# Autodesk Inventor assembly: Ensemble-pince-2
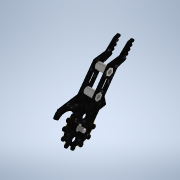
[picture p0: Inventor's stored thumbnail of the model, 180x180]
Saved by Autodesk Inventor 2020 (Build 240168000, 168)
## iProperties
Created: 2021-10
Part Number: Ensemble-pince-2
Document SubType Name: Assembly
Designer: bruno
Author: bruno
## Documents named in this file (4)
- C:\Users\bruno\Documents\1-Cours-2021-22\1SI\Challenge-2021\Pince-Inventor\Ensemble-pince-2.iam
- C:\Users\bruno\Documents\1-Cours-2021-22\1SI\Challenge-2021\Pince-Inventor\Ensemble-doigt-2.iam
- C:\Users\bruno\Documents\1-Cours-2021-22\1SI\Challenge-2021\Pince-Inventor\pince-2.ipt
- C:\Users\bruno\Documents\Inventor\Content Center Files\R2020\fr-FR\ANSI B18.6.7M(01)\ANSI B18.6.7M - M3x0,5 x 5(5).ipt
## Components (5 placed, 3 different names)
1. Ensemble-doigt-2:1 [sub-assembly] — Logement:1, Angle:1, Placage:5, Placage:6
2. pince-2:1 — Logement:1, Angle:1, Placage:1, Placage:2, Placage:3, Placage:4
3. Vis à tête tronconique à empreinte cruciforme - Type IA - Métrique M3x0,5 x 5:1 — Placage:1, Placage:2
4. Vis à tête tronconique à empreinte cruciforme - Type IA - Métrique M3x0,5 x 5:2 — Placage:3, Placage:4
5. Vis à tête tronconique à empreinte cruciforme - Type IA - Métrique M3x0,5 x 5:3 — Placage:5, Placage:6
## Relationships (8: Mate 6, Insert 1, Angle 1)
- Logement:1 [Insert]: Ensemble-doigt-2:1 ↔ pince-2:1
- Angle:1: Ensemble-doigt-2:1 ↔ pince-2:1
- Placage:1 [Mate]: pince-2:1 ↔ Vis à tête tronconique à empreinte cruciforme - Type IA - Métrique M3x0,5 x 5:1
- Placage:2 [Mate]: pince-2:1 ↔ Vis à tête tronconique à empreinte cruciforme - Type IA - Métrique M3x0,5 x 5:1
- Placage:3 [Mate]: pince-2:1 ↔ Vis à tête tronconique à empreinte cruciforme - Type IA - Métrique M3x0,5 x 5:2
- Placage:4 [Mate]: pince-2:1 ↔ Vis à tête tronconique à empreinte cruciforme - Type IA - Métrique M3x0,5 x 5:2
- Placage:5 [Mate]: Ensemble-doigt-2:1 ↔ Vis à tête tronconique à empreinte cruciforme - Type IA - Métrique M3x0,5 x 5:3
- Placage:6 [Mate]: Ensemble-doigt-2:1 ↔ Vis à tête tronconique à empreinte cruciforme - Type IA - Métrique M3x0,5 x 5:3
